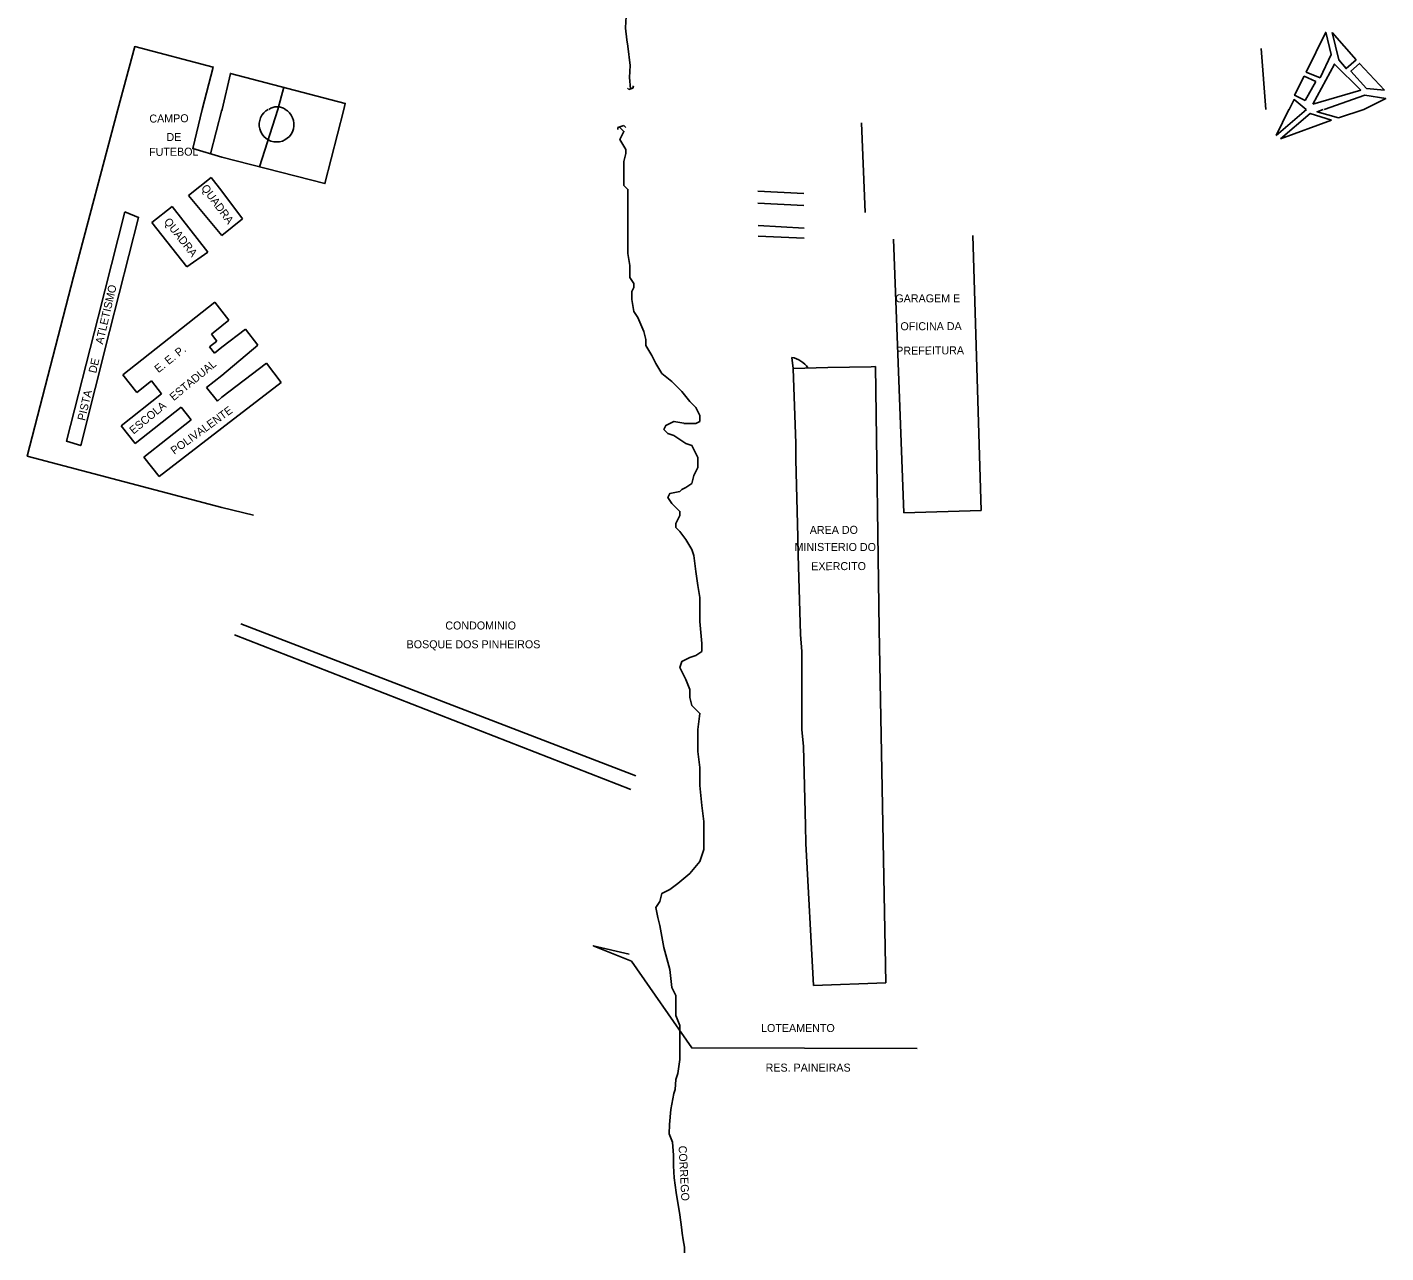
# Model space of a CAD drawing. Extents: x 325899 to 364828, y 7568995 to 7592502.
# Drawn here: x 335184 to 335863, y 7588930 to 7589543 of the extents above; entities that cross this region are included whole.
import ezdxf

# ---------------------------------------------------------------- set-up
doc = ezdxf.new("R2010")
doc.units = 0
for name, color, linetype in [('EDIFEXISTENT', 7, 'Continuous'), ('EDIFIDENTIF', 7, 'Continuous'), ('EDIFOBRAEXIS', 7, 'Continuous')]:
    doc.layers.add(name, color=color, linetype=linetype)

msp = doc.modelspace()

# ---------------------------------------------------------------- linework, layer by layer
at = {"layer": 'EDIFEXISTENT'}
for p, q in [((335484.9, 7589511.84), (335484.12, 7589512.48)), ((335486.8, 7589512.46), (335484.9, 7589511.84)), ((335487.21, 7589513.71), (335486.8, 7589512.46)), ((335479.39, 7589492.91), (335482.39, 7589493.91)), ((335479.39, 7589491.91), (335479.39, 7589492.91)), ((335482.39, 7589493.91), (335483.39, 7589492.91)), ((335276.08, 7589467.78), (335264.67, 7589458.8)), ((335281.39, 7589461.03), (335276.08, 7589467.78)), ((335264.67, 7589458.8), (335281.39, 7589438.79)), ((335281.39, 7589461.03), (335291.63, 7589447.18)), ((335246.39, 7589445.26), (335256.57, 7589453.27)), ((335256.57, 7589453.27), (335274.42, 7589430.58)), ((335263.82, 7589423.11), (335246.39, 7589445.26)), ((335291.63, 7589447.18), (335281.39, 7589438.79)), ((335622.37, 7589300.1), (335617.16, 7589437.01)), ((335656.82, 7589438.84), (335661.05, 7589301.29)), ((335274.42, 7589430.58), (335263.82, 7589423.11)), ((335277.88, 7589405.5), (335231.79, 7589369.24)), ((335281.39, 7589401.03), (335277.88, 7589405.5)), ((335281.39, 7589401.03), (335284.84, 7589396.52)), ((335284.84, 7589396.52), (335281.39, 7589393.68)), ((335281.39, 7589393.68), (335276.13, 7589389.54)), ((335276.13, 7589389.54), (335278.88, 7589386.05)), ((335281.39, 7589382.94), (335293.25, 7589391.97)), ((335293.25, 7589391.97), (335299.29, 7589384.04)), ((335278.88, 7589386.05), (335275.24, 7589383.18)), ((335275.24, 7589383.18), (335277.75, 7589379.99)), ((335277.75, 7589379.99), (335281.39, 7589382.94)), ((335299.29, 7589384.04), (335281.39, 7589368.9)), ((335281.39, 7589358), (335303.67, 7589374.98)), ((335303.67, 7589374.98), (335311.03, 7589365.33)), ((335231.79, 7589369.24), (335238.81, 7589360.31)), ((335281.39, 7589368.9), (335273.76, 7589362.9)), ((335566.94, 7589372.41), (335584.39, 7589372.91)), ((335568.39, 7589334.91), (335566.94, 7589372.41)), ((335584.39, 7589372.91), (335606, 7589373.19)), ((335606, 7589373.19), (335608.24, 7589373.27)), ((335608.24, 7589373.27), (335610.05, 7589242.07)), ((335238.81, 7589360.31), (335246.17, 7589366.1)), ((335246.17, 7589366.1), (335251.26, 7589359.62)), ((335273.76, 7589362.9), (335279.21, 7589355.97)), ((335311.03, 7589365.33), (335281.39, 7589342.48)), ((335251.26, 7589359.62), (335231, 7589343.68)), ((335279.21, 7589355.97), (335281.39, 7589358)), ((335237.98, 7589334.81), (335261.06, 7589352.97)), ((335261.06, 7589352.97), (335266.07, 7589346.6)), ((335231, 7589343.68), (335237.98, 7589334.81)), ((335266.07, 7589346.6), (335242.42, 7589327.99)), ((335250.02, 7589318.33), (335281.39, 7589342.48)), ((335568.39, 7589326.91), (335568.39, 7589334.91)), ((335242.42, 7589327.99), (335250.02, 7589318.33)), ((335569.36, 7589288.01), (335568.39, 7589326.91)), ((335661.05, 7589301.29), (335622.37, 7589300.1)), ((335569.45, 7589279.23), (335569.36, 7589288.01)), ((335570.72, 7589239.31), (335569.45, 7589279.23)), ((335571.39, 7589230.91), (335570.72, 7589239.31)), ((335610.05, 7589242.07), (335613.29, 7589065.16)), ((335571.39, 7589191.91), (335571.39, 7589230.91)), ((335572.16, 7589183.39), (335571.39, 7589191.91)), ((335573.22, 7589143.8), (335572.16, 7589183.39)), ((335573.39, 7589134.91), (335573.22, 7589143.8)), ((335577.21, 7589063.8), (335573.39, 7589134.91)), ((335613.29, 7589065.16), (335577.21, 7589063.8))]:
    msp.add_line(p, q, dxfattribs=at)
at = {"layer": 'EDIFOBRAEXIS'}
for points in [[(335478.27, 7589596.74), (335477.77, 7589590.79), (335477.75, 7589589.49), (335477.77, 7589586.8), (335478.94, 7589582.96), (335480.34, 7589578.71), (335479.41, 7589571.67), (335480.61, 7589564.92), (335483.23, 7589559.93), (335484.44, 7589554.22), (335483.44, 7589548.17), (335483.37, 7589545.75), (335483.2, 7589542.47), (335483.79, 7589536.69), (335484.43, 7589533.48), (335485.5, 7589523.75), (335485.22, 7589517.82), (335485.76, 7589512.12)], [(335830.47, 7589517.7), (335823.57, 7589520.56), (335833.26, 7589540.42), (335836.02, 7589529.34)], [(335836.42, 7589540.27), (335839.79, 7589526.74), (335843.43, 7589522.31), (335848.5, 7589526.62)], [(335836.42, 7589540.27), (335848.5, 7589526.62)], [(335229.33, 7589501.91), (335237.85, 7589533.25), (335277.06, 7589523), (335271.5, 7589501.91)], [(335801.07, 7589532.33), (335803.33, 7589501.91)], [(335826.83, 7589504.56), (335837.71, 7589524.51), (335850.88, 7589511.52)], [(335836.02, 7589529.34), (335830.47, 7589517.7)], [(335862.58, 7589511.53), (335850.1, 7589524.86), (335845.88, 7589520.92), (335853.7, 7589512.35)], [(335281.54, 7589501.91), (335285.67, 7589519.89), (335343.08, 7589504.89), (335342.42, 7589501.91)], [(335823.03, 7589506.33), (335817.68, 7589508.94), (335822.55, 7589518.45), (335828.4, 7589515.88)], [(335309.31, 7589501.91), (335312.31, 7589512.93)], [(335828.4, 7589515.88), (335823.03, 7589506.33)], [(335850.88, 7589511.52), (335826.83, 7589504.56)], [(335853.7, 7589512.35), (335862.58, 7589511.53)], [(335815, 7589501.91), (335817.45, 7589506.77), (335823.43, 7589501.91)], [(335832.41, 7589501.91), (335852.84, 7589509.01), (335863.32, 7589507.33), (335852.27, 7589501.91)], [(335229.33, 7589501.91), (335207.28, 7589418.12), (335184.04, 7589328.46), (335281.39, 7589302.9)], [(335271.5, 7589501.91), (335266.86, 7589482.25), (335281.39, 7589477.93)], [(335281.39, 7589501.59), (335275.78, 7589479.6)], [(335342.42, 7589501.91), (335332.94, 7589464.77), (335281.39, 7589477.93)], [(335281.54, 7589501.91), (335281.39, 7589501.39)], [(335309.31, 7589501.91), (335300.19, 7589473.13)], [(335823.58, 7589501.91), (335808.54, 7589488.83)], [(335814.76, 7589501.91), (335808.54, 7589488.83)], [(335836.22, 7589496.43), (335825.57, 7589499.86), (335810.63, 7589487.1)], [(335831.93, 7589501.91), (335828.93, 7589500.68), (335839.64, 7589497.68)], [(335852.27, 7589501.91), (335839.64, 7589497.68)], [(335480.39, 7589492.91), (335482.39, 7589490.91), (335480.39, 7589486.91), (335483.39, 7589481.91), (335483.39, 7589479.91), (335482.39, 7589475.91), (335482.39, 7589470.91), (335482.39, 7589468.91), (335482.39, 7589467.91), (335482.39, 7589463.91), (335484.39, 7589461.91), (335484.39, 7589458.91), (335484.39, 7589449.91), (335484.39, 7589440.91), (335484.39, 7589435.91), (335484.39, 7589429.91), (335485.39, 7589423.91), (335485.39, 7589417.91), (335487.39, 7589414.91), (335487.39, 7589412.91), (335486.39, 7589410.91), (335486.39, 7589406.91), (335487.39, 7589400.91), (335489.39, 7589397.91), (335492.39, 7589390.91), (335493.39, 7589386.91), (335493.39, 7589383.91), (335496.39, 7589378.91), (335498.39, 7589374.91), (335501.39, 7589369.91), (335506.39, 7589365.91), (335509.39, 7589362.91), (335511.39, 7589360.91), (335515.39, 7589355.91), (335518.39, 7589352.91), (335519.39, 7589350.91), (335520.39, 7589348.91), (335520.39, 7589346.91), (335520.39, 7589345.91), (335518.39, 7589344.91), (335517.39, 7589344.91), (335516.39, 7589344.91), (335514.39, 7589344.91), (335512.39, 7589344.91), (335513.39, 7589344.91), (335507.39, 7589345.91), (335505.39, 7589344.91), (335503.39, 7589343.91), (335502.39, 7589341.91), (335504.39, 7589339.91), (335507.39, 7589338.91), (335513.39, 7589334.91), (335516.39, 7589333.91), (335519.39, 7589327.91), (335519.39, 7589322.91), (335517.39, 7589318.91), (335516.39, 7589314.91), (335513.39, 7589312.91), (335511.39, 7589311.91), (335510.39, 7589310.91), (335505.39, 7589309.91), (335504.39, 7589307.91), (335506.39, 7589304.91), (335506.39, 7589304.91), (335508.39, 7589302.91), (335510.39, 7589300.91), (335510.39, 7589298.91), (335509.39, 7589296.91), (335508.39, 7589294.91), (335508.39, 7589292.91), (335510.39, 7589290.91), (335513.39, 7589286.91), (335516.39, 7589281.91), (335517.39, 7589278.91), (335518.39, 7589270.91), (335519.39, 7589263.91), (335520.39, 7589257.91), (335520.39, 7589245.91), (335521.39, 7589234.91), (335521.39, 7589230.91), (335518.39, 7589228.91), (335515.39, 7589227.91), (335511.39, 7589225.91), (335510.39, 7589222.91), (335513.39, 7589216.91), (335515.39, 7589211.91), (335515.39, 7589207.91), (335516.39, 7589203.91), (335520.39, 7589199.91), (335519.39, 7589191.91), (335519.39, 7589180.91), (335520.39, 7589172.91), (335520.39, 7589163.91), (335521.39, 7589153.91), (335522.39, 7589145.91), (335522.39, 7589137.91), (335522.39, 7589131.91), (335520.39, 7589125.91), (335515.39, 7589119.91), (335509.39, 7589114.91), (335505.39, 7589111.91), (335501.39, 7589109.91), (335500.39, 7589105.91), (335498.39, 7589102.91), (335499.39, 7589097.91), (335500.39, 7589093.91), (335502.39, 7589082.91), (335505.39, 7589071.91), (335506.39, 7589062.91), (335508.39, 7589058.91), (335508.39, 7589048.91), (335510.39, 7589043.91), (335510.39, 7589039.91), (335510.39, 7589031.91), (335510.39, 7589026.91), (335509.39, 7589019.91), (335508.33, 7589016.91), (335508.02, 7589011.91), (335507.39, 7589009.91), (335505.91, 7589001.91)], [(335602.93, 7589450.4), (335601.19, 7589495.24)], [(335836.22, 7589496.43), (335810.63, 7589487.1)], [(335572.34, 7589459.85), (335549.39, 7589460.92)], [(335232.94, 7589450.67), (335239.71, 7589447.84), (335225.23, 7589390.9), (335210.81, 7589333.81), (335203.69, 7589336.07), (335219.47, 7589398.05), (335232.94, 7589450.67)], [(335572.34, 7589453.91), (335549.42, 7589454.95)], [(335572.49, 7589442.54), (335549.48, 7589443.87)], [(335572.54, 7589437.43), (335549.54, 7589438.42)], [(335566.39, 7589377.91), (335566.94, 7589372.41)], [(335281.39, 7589302.9), (335297.12, 7589298.96)], [(335485.85, 7589161.89), (335287.63, 7589239.13)], [(335290.79, 7589244.7), (335488.32, 7589168.66)], [(335485.06, 7589079.5), (335467.05, 7589083.74), (335486.18, 7589075.95), (335516.27, 7589032.64), (335629.01, 7589032.32)], [(335505.91, 7589001.91), (335505.17, 7588994.38), (335505.04, 7588989.77), (335506.61, 7588985.61), (335507.18, 7588979.05), (335507.19, 7588973.64), (335507.47, 7588967.73), (335508.46, 7588960.29), (335510.29, 7588949.22), (335511.1, 7588943.11), (335511.44, 7588940.07), (335512.03, 7588936.72), (335512.61, 7588932.99), (335512.71, 7588930.21)]]:
    msp.add_lwpolyline(points, dxfattribs=at)
for centre, radius, start, end in [((335308.76, 7589494.29), 8.7, 118.82156, 61.17844), ((335309.03, 7589495.71), 7.49, 55.91931, 124.08069), ((335563.91, 7589365.45), 12.71, 34.383, 78.75004)]:
    msp.add_arc(centre, radius, start, end, dxfattribs=at)

# ---------------------------------------------------------------- texts
at = {"layer": 'EDIFIDENTIF'}
for s, rotation, p in [('CAMPO ', 0.58076, (335245.16, 7589495.28)), ('DE', 0.01038, (335253.67, 7589486.07)), ('FUTEBOL', 0.35663, (335245.02, 7589478.62)), ('QUADRA', 306.42417, (335270.83, 7589462.54)), ('QUADRA', 308.24557, (335252.19, 7589445.7)), ('PISTA      DE     ATLETISMO', 76.83267, (335212.96, 7589345.99)), ('GARAGEM E', 359.97746, (335618.11, 7589405.42)), ('OFICINA DA', 0.12979, (335620.65, 7589391.46)), ('E. E. P.', 38.52151, (335249.65, 7589369.94)), ('PREFEITURA', 0.38205, (335618.54, 7589379.23)), ('ESCOLA   ESTADUAL', 39.71058, (335237.19, 7589339.24)), ('POLIVALENTE', 35.95098, (335257.6, 7589329.13)), ('AREA DO', 0.23675, (335575.32, 7589289.59)), ('MINISTERIO DO', 359.88826, (335567.69, 7589281.16)), ('EXERCITO', 0.15751, (335576.06, 7589271.49)), ('CORREGO', 272.99435, (335509.71, 7588983.69))]:
    msp.add_text(s, height=4, rotation=rotation, dxfattribs=at).set_placement(p)
for s, p in [('CONDOMINIO', (335393.09, 7589241.85)), ('BOSQUE DOS PINHEIROS', (335373.75, 7589232.46)), ('LOTEAMENTO', (335550.96, 7589040.59)), ('RES. PAINEIRAS', (335553.24, 7589020.81))]:
    msp.add_text(s, height=4, dxfattribs=at).set_placement(p)

doc.saveas('drawing.dxf')
